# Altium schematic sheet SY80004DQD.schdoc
size 127 x 101 mm
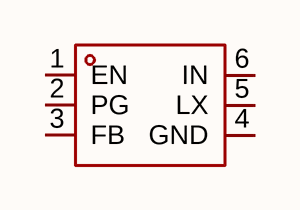
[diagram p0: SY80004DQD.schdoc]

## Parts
U?  sy80004dqd  [VSON-6_L1.5-W1.5-P0.50-TL]  (value not drawn)

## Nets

Not connected (* = marked no-connect by the designer): U? 1(EN) 2(PG) 3(FB) 4(GND) 5(LX) 6(IN)

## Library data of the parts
U? = sy80004dqd: 功能类型:降压型;工作电压:2.5V~5.5V;输出电压:-;输出电流:4A;输出类型:可调;; Manufacturer: Silergy(矽力杰); AddInBom: yes; ModelId: 37fa624c5eb24c8ea34f41f611b7d8b8; ModelTransform: 59.055,59.8424,0,270,0,0,4.961,0,0; Function: 降压型; Output Current: 4A; Frequency - Switching: 2.2MHz; Synchronous Rectifier: 是; Number of Outputs: 1; Topology: 降压式; Quiescent Current: 21uA; Switch tube (built-in/external): 内置; Output Type: 可调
